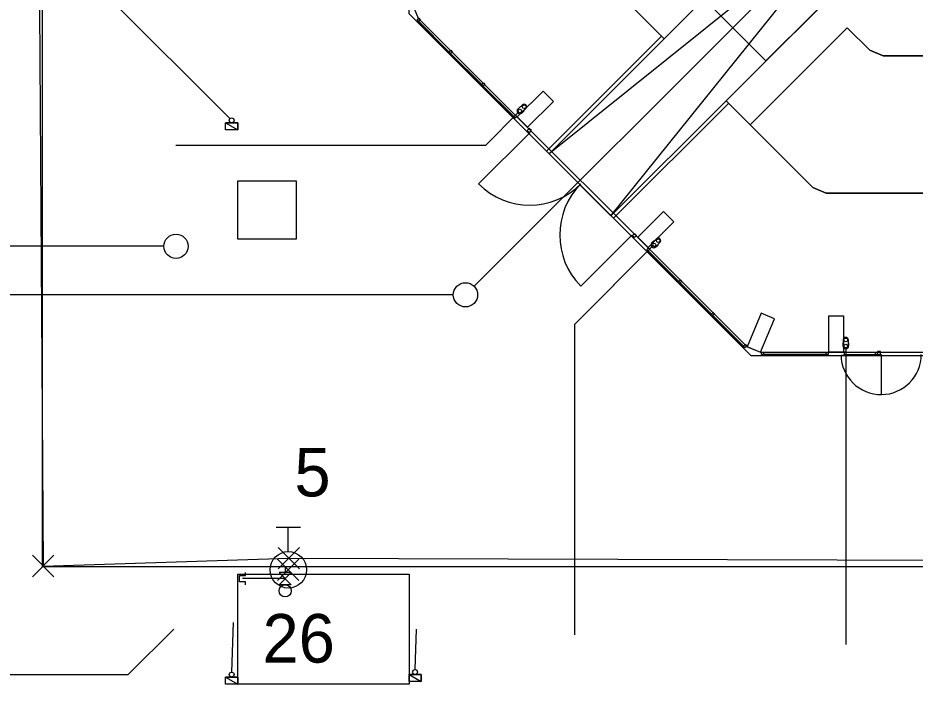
# Model space of a CAD drawing. Extents: x -263964 to -263544, y -1242317 to -1242020.
# Drawn here: x -263925.14 to -263888.22, y -1242254.98 to -1242227.54 of the extents above; entities that cross this region are included whole.
import ezdxf

# ---------------------------------------------------------------- set-up
doc = ezdxf.new("R2010")
doc.units = 0
for name, color, linetype in [('KFA_KOORDINACNA_SITUACIA_DSP_SEDA', 7, 'Continuous'), ('KFA_SO_50-2_POZIARNY_VODOVOD_BODY', 7, 'Continuous'), ('KFA_SO_50-2_POZIARNY_VODOVOD_NADZEMNE_PRVKY', 7, 'Continuous'), ('KFA_SO_50-2_POZIARNY_VODOVOD_TRASA', 7, 'Continuous')]:
    doc.layers.add(name, color=color, linetype=linetype)

msp = doc.modelspace()

# ---------------------------------------------------------------- linework, layer by layer
at = {"layer": 'KFA_KOORDINACNA_SITUACIA_DSP_SEDA'}
for p, q in [((-263924.143, -1242185.14), (-263924.143, -1242250.14)), ((-263889.023, -1242221.253), (-263906.365, -1242238.596)), ((-263916.414, -1242231.691), (-263926.24, -1242221.865)), ((-263908.893, -1242226.995), (-263908.663, -1242227.55)), ((-263908.709, -1242227.631), (-263908.638, -1242227.56)), ((-263908.68, -1242227.659), (-263908.709, -1242227.631)), ((-263908.685, -1242227.654), (-263908.703, -1242227.672)), ((-263907.377, -1242228.963), (-263908.685, -1242227.654)), ((-263908.663, -1242227.55), (-263895.135, -1242241.078)), ((-263908.581, -1242227.617), (-263908.652, -1242227.688)), ((-263908.638, -1242227.56), (-263908.581, -1242227.617)), ((-263908.703, -1242227.672), (-263907.395, -1242228.98)), ((-263908.652, -1242227.688), (-263908.68, -1242227.659)), ((-263895.005, -1242231.945), (-263891.01, -1242227.95)), ((-263891.01, -1242227.95), (-263890.082, -1242228.878)), ((-263907.395, -1242228.98), (-263907.377, -1242228.963)), ((-263907.39, -1242228.95), (-263907.319, -1242228.879)), ((-263907.361, -1242228.978), (-263907.39, -1242228.95)), ((-263907.363, -1242229.012), (-263907.345, -1242228.994)), ((-263906.055, -1242230.32), (-263907.363, -1242229.012)), ((-263907.333, -1242229.007), (-263907.361, -1242228.978)), ((-263907.345, -1242228.994), (-263906.037, -1242230.303)), ((-263907.262, -1242228.936), (-263907.333, -1242229.007)), ((-263907.319, -1242228.879), (-263907.262, -1242228.936)), ((-263890.082, -1242228.878), (-263889.528, -1242229.107)), ((-263889.528, -1242229.107), (-263874.98, -1242229.107)), ((-263906.046, -1242230.294), (-263905.975, -1242230.223)), ((-263905.975, -1242230.223), (-263905.918, -1242230.28)), ((-263906.037, -1242230.303), (-263906.055, -1242230.32)), ((-263906.017, -1242230.322), (-263906.046, -1242230.294)), ((-263906.019, -1242230.356), (-263906.001, -1242230.338)), ((-263904.711, -1242231.664), (-263906.019, -1242230.356)), ((-263905.989, -1242230.351), (-263906.017, -1242230.322)), ((-263906.001, -1242230.338), (-263904.693, -1242231.647)), ((-263905.918, -1242230.28), (-263905.989, -1242230.351)), ((-263903.526, -1242230.561), (-263904.586, -1242231.622)), ((-263903.101, -1242230.985), (-263903.526, -1242230.561)), ((-263904.484, -1242231.218), (-263904.563, -1242231.296)), ((-263904.465, -1242231.218), (-263904.484, -1242231.218)), ((-263904.376, -1242231.13), (-263904.465, -1242231.218)), ((-263904.231, -1242231.275), (-263904.319, -1242231.364)), ((-263904.162, -1242232.046), (-263903.101, -1242230.985)), ((-263904.533, -1242231.432), (-263905.894, -1242232.793)), ((-263904.726, -1242231.613), (-263904.656, -1242231.543)), ((-263904.698, -1242231.642), (-263904.726, -1242231.613)), ((-263904.693, -1242231.647), (-263904.711, -1242231.664)), ((-263904.67, -1242231.67), (-263904.698, -1242231.642)), ((-263904.599, -1242231.599), (-263904.67, -1242231.67)), ((-263904.656, -1242231.543), (-263904.599, -1242231.599)), ((-263904.586, -1242231.622), (-263904.162, -1242232.046)), ((-263904.397, -1242231.462), (-263904.319, -1242231.383)), ((-263904.319, -1242231.383), (-263904.397, -1242231.462)), ((-263904.319, -1242231.364), (-263904.319, -1242231.383)), ((-263916.593, -1242231.862), (-263916.093, -1242231.862)), ((-263916.593, -1242232.152), (-263916.593, -1242231.862)), ((-263916.593, -1242231.862), (-263916.093, -1242232.152)), ((-263916.593, -1242231.862), (-263916.093, -1242232.152)), ((-263916.093, -1242231.862), (-263916.593, -1242231.862)), ((-263916.093, -1242231.862), (-263916.093, -1242232.152)), ((-263916.093, -1242232.152), (-263916.093, -1242231.862)), ((-263892.422, -1242234.528), (-263895.005, -1242231.945)), ((-263916.093, -1242232.152), (-263916.593, -1242232.152)), ((-263904.074, -1242232.281), (-263906.177, -1242234.384)), ((-263904.091, -1242232.093), (-263904.176, -1242232.178)), ((-263904.176, -1242232.178), (-263904.091, -1242232.263)), ((-263904.006, -1242232.178), (-263904.091, -1242232.093)), ((-263904.091, -1242232.263), (-263904.006, -1242232.178)), ((-263904.091, -1242232.263), (-263904.074, -1242232.281)), ((-263905.894, -1242232.793), (-263918.643, -1242232.793)), ((-263916.093, -1242234.257), (-263913.693, -1242234.257)), ((-263916.093, -1242236.657), (-263916.093, -1242234.257)), ((-263913.693, -1242234.257), (-263913.693, -1242236.657)), ((-263891.868, -1242234.757), (-263892.422, -1242234.528)), ((-263874.98, -1242234.757), (-263891.868, -1242234.757)), ((-263899.631, -1242236.576), (-263898.571, -1242235.516)), ((-263898.571, -1242235.516), (-263898.147, -1242235.94)), ((-263898.147, -1242235.94), (-263899.207, -1242237.001)), ((-263899.866, -1242236.488), (-263901.97, -1242238.592)), ((-263899.849, -1242236.506), (-263899.764, -1242236.421)), ((-263899.764, -1242236.591), (-263899.849, -1242236.506)), ((-263899.764, -1242236.421), (-263899.679, -1242236.506)), ((-263899.679, -1242236.506), (-263899.764, -1242236.591)), ((-263913.693, -1242236.657), (-263916.093, -1242236.657)), ((-263899.207, -1242237.001), (-263899.631, -1242236.576)), ((-263898.969, -1242236.733), (-263899.047, -1242236.812)), ((-263898.949, -1242236.733), (-263898.969, -1242236.733)), ((-263898.861, -1242236.645), (-263898.949, -1242236.733)), ((-263898.715, -1242236.791), (-263898.804, -1242236.879)), ((-263898.804, -1242236.879), (-263898.804, -1242236.899)), ((-263919.13, -1242236.949), (-263926.43, -1242236.949)), ((-263898.965, -1242236.895), (-263902.238, -1242240.168)), ((-263899.018, -1242236.948), (-263902.238, -1242240.168)), ((-263899.185, -1242237.014), (-263899.255, -1242237.084)), ((-263899.255, -1242237.084), (-263899.227, -1242237.113)), ((-263899.232, -1242237.108), (-263899.25, -1242237.125)), ((-263899.25, -1242237.125), (-263897.942, -1242238.434)), ((-263897.924, -1242238.416), (-263899.232, -1242237.108)), ((-263899.227, -1242237.113), (-263899.199, -1242237.141)), ((-263899.199, -1242237.141), (-263899.128, -1242237.07)), ((-263899.128, -1242237.07), (-263899.185, -1242237.014)), ((-263898.804, -1242236.899), (-263898.882, -1242236.977)), ((-263898.882, -1242236.977), (-263898.804, -1242236.899)), ((-263897.865, -1242238.333), (-263897.936, -1242238.404)), ((-263897.809, -1242238.389), (-263897.865, -1242238.333)), ((-263897.942, -1242238.434), (-263897.924, -1242238.416)), ((-263897.936, -1242238.404), (-263897.908, -1242238.432)), ((-263897.908, -1242238.432), (-263897.88, -1242238.46)), ((-263897.888, -1242238.452), (-263897.906, -1242238.469)), ((-263897.906, -1242238.469), (-263896.598, -1242239.778)), ((-263896.58, -1242239.76), (-263897.888, -1242238.452)), ((-263897.88, -1242238.46), (-263897.809, -1242238.389)), ((-263907.219, -1242238.949), (-263926.43, -1242238.949)), ((-263896.598, -1242239.778), (-263896.58, -1242239.76)), ((-263896.522, -1242239.677), (-263896.592, -1242239.748)), ((-263896.592, -1242239.748), (-263896.564, -1242239.776)), ((-263896.566, -1242239.809), (-263896.548, -1242239.792)), ((-263895.258, -1242241.118), (-263896.566, -1242239.809)), ((-263896.564, -1242239.776), (-263896.536, -1242239.804)), ((-263896.548, -1242239.792), (-263895.24, -1242241.1)), ((-263896.536, -1242239.804), (-263896.465, -1242239.733)), ((-263896.465, -1242239.733), (-263896.522, -1242239.677)), ((-263894.551, -1242239.702), (-263895.125, -1242241.088)), ((-263893.997, -1242239.932), (-263894.551, -1242239.702)), ((-263891.768, -1242241.312), (-263891.768, -1242239.812)), ((-263891.768, -1242239.812), (-263891.168, -1242239.812)), ((-263891.168, -1242239.812), (-263891.168, -1242241.312)), ((-263902.238, -1242240.168), (-263902.238, -1242252.949)), ((-263894.571, -1242241.318), (-263893.997, -1242239.932)), ((-263891.171, -1242240.932), (-263891.185, -1242240.946)), ((-263891.185, -1242240.946), (-263891.185, -1242241.057)), ((-263891.171, -1242240.807), (-263891.171, -1242240.932)), ((-263890.965, -1242240.807), (-263890.965, -1242240.932)), ((-263890.965, -1242240.932), (-263890.951, -1242240.946)), ((-263890.951, -1242241.057), (-263890.951, -1242240.946)), ((-263890.951, -1242240.946), (-263890.951, -1242241.057)), ((-263895.202, -1242240.996), (-263895.273, -1242241.067)), ((-263895.273, -1242241.067), (-263895.245, -1242241.095)), ((-263895.24, -1242241.1), (-263895.258, -1242241.118)), ((-263895.245, -1242241.095), (-263895.216, -1242241.123)), ((-263895.216, -1242241.123), (-263895.146, -1242241.053)), ((-263895.146, -1242241.053), (-263895.202, -1242240.996)), ((-263895.135, -1242241.078), (-263894.581, -1242241.307)), ((-263895.125, -1242241.088), (-263894.571, -1242241.318)), ((-263894.581, -1242241.307), (-263809.355, -1242241.307)), ((-263894.531, -1242241.407), (-263894.531, -1242241.307)), ((-263894.531, -1242241.307), (-263894.451, -1242241.307)), ((-263894.451, -1242241.307), (-263894.451, -1242241.407)), ((-263891.868, -1242241.407), (-263891.868, -1242241.307)), ((-263891.868, -1242241.307), (-263891.788, -1242241.307)), ((-263891.788, -1242241.307), (-263891.788, -1242241.407)), ((-263891.168, -1242241.312), (-263891.768, -1242241.312)), ((-263891.058, -1242241.307), (-263891.138, -1242241.307)), ((-263891.138, -1242241.307), (-263891.138, -1242241.407)), ((-263891.068, -1242241.132), (-263891.068, -1242253.353)), ((-263891.058, -1242241.407), (-263891.058, -1242241.307)), ((-263889.838, -1242241.407), (-263889.838, -1242241.307)), ((-263889.838, -1242241.307), (-263889.758, -1242241.307)), ((-263889.638, -1242241.287), (-263889.758, -1242241.287)), ((-263889.758, -1242241.287), (-263889.758, -1242241.407)), ((-263889.758, -1242241.307), (-263889.758, -1242241.407)), ((-263889.638, -1242241.407), (-263889.638, -1242241.287)), ((-263894.491, -1242241.407), (-263894.531, -1242241.407)), ((-263894.451, -1242241.407), (-263894.491, -1242241.407)), ((-263891.828, -1242241.407), (-263894.478, -1242241.407)), ((-263894.478, -1242241.407), (-263894.478, -1242241.432)), ((-263894.478, -1242241.432), (-263891.828, -1242241.432)), ((-263891.828, -1242241.407), (-263891.868, -1242241.407)), ((-263891.828, -1242241.432), (-263891.828, -1242241.407)), ((-263891.788, -1242241.407), (-263891.828, -1242241.407)), ((-263891.263, -1242241.432), (-263889.613, -1242241.432)), ((-263891.138, -1242241.407), (-263891.098, -1242241.407)), ((-263891.098, -1242241.432), (-263891.098, -1242241.407)), ((-263891.098, -1242241.407), (-263889.798, -1242241.407)), ((-263891.098, -1242241.407), (-263891.058, -1242241.407)), ((-263889.798, -1242241.432), (-263891.098, -1242241.432)), ((-263889.798, -1242241.407), (-263889.838, -1242241.407)), ((-263889.798, -1242241.407), (-263889.798, -1242241.432)), ((-263889.758, -1242241.407), (-263889.798, -1242241.407)), ((-263889.758, -1242241.407), (-263889.638, -1242241.407)), ((-263889.638, -1242241.407), (-263889.613, -1242241.407)), ((-263889.613, -1242241.407), (-263889.613, -1242243.057)), ((-263924.143, -1242250.14), (-263788.143, -1242250.14)), ((-263914.143, -1242250.14), (-263914.143, -1242250.39)), ((-263914.143, -1242250.14), (-263914.143, -1242250.39)), ((-263916.093, -1242254.982), (-263916.093, -1242250.458)), ((-263916.093, -1242250.458), (-263909.043, -1242250.458)), ((-263916.018, -1242250.515), (-263915.768, -1242250.515)), ((-263916.018, -1242250.765), (-263916.018, -1242250.515)), ((-263915.768, -1242250.515), (-263915.768, -1242250.39)), ((-263914.393, -1242250.39), (-263913.893, -1242250.89)), ((-263913.893, -1242250.39), (-263914.393, -1242250.39)), ((-263914.393, -1242250.89), (-263913.893, -1242250.39)), ((-263909.043, -1242250.458), (-263909.043, -1242254.982)), ((-263915.768, -1242250.765), (-263916.018, -1242250.765)), ((-263914.143, -1242250.64), (-263915.893, -1242250.64)), ((-263915.768, -1242250.89), (-263915.768, -1242250.765)), ((-263913.893, -1242250.89), (-263914.393, -1242250.89)), ((-263920.595, -1242254.592), (-263918.723, -1242252.72)), ((-263916.339, -1242254.492), (-263916.265, -1242252.443)), ((-263908.789, -1242254.387), (-263908.729, -1242252.715)), ((-263929.73, -1242254.592), (-263920.595, -1242254.592)), ((-263909.043, -1242254.587), (-263908.543, -1242254.587)), ((-263909.043, -1242254.877), (-263909.043, -1242254.587)), ((-263909.043, -1242254.587), (-263908.543, -1242254.877)), ((-263909.043, -1242254.587), (-263908.543, -1242254.877)), ((-263908.543, -1242254.587), (-263909.043, -1242254.587)), ((-263908.543, -1242254.587), (-263908.543, -1242254.877)), ((-263908.543, -1242254.877), (-263908.543, -1242254.587)), ((-263916.593, -1242254.692), (-263916.093, -1242254.692)), ((-263916.593, -1242254.982), (-263916.593, -1242254.692)), ((-263916.593, -1242254.692), (-263916.093, -1242254.982)), ((-263916.593, -1242254.692), (-263916.093, -1242254.982)), ((-263916.093, -1242254.692), (-263916.593, -1242254.692)), ((-263916.093, -1242254.692), (-263916.093, -1242254.982)), ((-263916.093, -1242254.982), (-263916.093, -1242254.692)), ((-263908.543, -1242254.877), (-263909.043, -1242254.877)), ((-263916.093, -1242254.982), (-263916.593, -1242254.982)), ((-263909.043, -1242254.982), (-263916.093, -1242254.982))]:
    msp.add_line(p, q, dxfattribs=at)
for points in [[(-263794.893, -1242227.382), (-263808.968, -1242241.457), (-263894.968, -1242241.457), (-263909.043, -1242227.382), (-263909.043, -1242196.333), (-263914.143, -1242196.333), (-263914.143, -1242132.433), (-263909.043, -1242132.433), (-263909.043, -1242101.382), (-263894.968, -1242087.307), (-263808.968, -1242087.307), (-263794.893, -1242101.382), (-263794.893, -1242227.382)], [(-263816.02, -1242224.432), (-263887.916, -1242224.432), (-263888.26, -1242224.088), (-263889.254, -1242226.488), (-263890.391, -1242225.351), (-263894.351, -1242229.311), (-263896.896, -1242226.765), (-263892.937, -1242222.806), (-263894.073, -1242221.669), (-263891.673, -1242220.675), (-263892.018, -1242220.33), (-263892.018, -1242181.432), (-263893.618, -1242181.432), (-263893.618, -1242147.332), (-263892.018, -1242147.332), (-263892.018, -1242108.434)], [(-263898.543, -1242228.407), (-263902.112, -1242224.837), (-263902.343, -1242224.282), (-263902.343, -1242203.332), (-263909.043, -1242203.332)], [(-263891.673, -1242220.675), (-263894.073, -1242221.669), (-263892.937, -1242222.806), (-263898.544, -1242228.407)], [(-263895.995, -1242230.956), (-263890.391, -1242225.352), (-263889.254, -1242226.488), (-263888.26, -1242224.088), (-263891.673, -1242220.675)], [(-263903.277, -1242233.148), (-263900.731, -1242235.694), (-263890.333, -1242222.748), (-263903.277, -1242233.148)], [(-263898.65, -1242228.301), (-263903.39, -1242233.035), (-263900.629, -1242235.796), (-263895.875, -1242231.049)], [(-263898.544, -1242228.407), (-263903.281, -1242233.144), (-263900.731, -1242235.694), (-263895.982, -1242230.943)], [(-263807.942, -1242230.956), (-263811.512, -1242234.526), (-263812.068, -1242234.757), (-263891.868, -1242234.757), (-263892.424, -1242234.526), (-263895.994, -1242230.956)]]:
    msp.add_lwpolyline(points, dxfattribs=at)
msp.add_lwpolyline([(-263891.01, -1242227.95), (-263895.005, -1242231.945), (-263892.422, -1242234.528), (-263891.868, -1242234.757), (-263874.98, -1242234.757), (-263874.98, -1242229.107), (-263889.528, -1242229.107), (-263890.082, -1242228.878)], close=True, dxfattribs=at)
for centre, radius in [((-263904.48, -1242231.379), 0.075), ((-263904.303, -1242231.202), 0.075), ((-263916.343, -1242231.762), 0.1), ((-263918.63, -1242236.949), 0.5), ((-263898.965, -1242236.895), 0.075), ((-263898.788, -1242236.718), 0.075), ((-263906.719, -1242238.949), 0.5), ((-263891.068, -1242240.807), 0.075), ((-263891.068, -1242241.057), 0.075), ((-263914.143, -1242251.14), 0.25), ((-263916.343, -1242254.592), 0.1), ((-263908.793, -1242254.487), 0.1)]:
    msp.add_circle(centre, radius, dxfattribs=at)
for centre, radius, start, end in [((-263904.48, -1242231.379), 0.117, 135, 315), ((-263904.303, -1242231.202), 0.103, 315, 135), ((-263904.074, -1242232.281), 2.975, 225.0001, 315.0001), ((-263899.866, -1242236.488), 2.975, 134.9999, 224.9999), ((-263898.965, -1242236.895), 0.117, 135, 315), ((-263898.788, -1242236.718), 0.103, 315, 135), ((-263891.068, -1242240.807), 0.103, 360, 180), ((-263891.068, -1242241.057), 0.117, 180, 360), ((-263889.613, -1242241.407), 1.65, 180.8682, 0)]:
    msp.add_arc(centre, radius, start, end, dxfattribs=at)
at = {"layer": 'KFA_SO_50-2_POZIARNY_VODOVOD_BODY'}
for p, q in [((-263914.428, -1242250.24), (-263913.544, -1242249.356)), ((-263913.544, -1242250.24), (-263914.428, -1242249.356)), ((-263924.542, -1242250.563), (-263923.658, -1242249.679)), ((-263923.658, -1242250.563), (-263924.542, -1242249.679)), ((-263913.986, -1242249.798), (-263913.986, -1242249.798)), ((-263924.1, -1242250.121), (-263924.1, -1242250.121)), ((-263914.455, -1242250.719), (-263913.571, -1242249.835)), ((-263913.571, -1242250.719), (-263914.455, -1242249.835)), ((-263914.013, -1242250.277), (-263914.013, -1242250.277))]:
    msp.add_line(p, q, dxfattribs=at)
at = {"layer": 'KFA_SO_50-2_POZIARNY_VODOVOD_NADZEMNE_PRVKY'}
for points in [[(-263913.513, -1242248.527), (-263914.513, -1242248.527)], [(-263914.013, -1242249.527), (-263914.013, -1242248.527)]]:
    msp.add_lwpolyline(points, dxfattribs=at)
msp.add_circle((-263914.013, -1242250.277), 0.75, dxfattribs=at)
at = {"layer": 'KFA_SO_50-2_POZIARNY_VODOVOD_TRASA'}
msp.add_lwpolyline([(-263924.931, -1242185.127), (-263924.146, -1242197.091), (-263924.296, -1242220.899), (-263924.1, -1242250.121), (-263913.986, -1242249.798), (-263886.91, -1242249.876), (-263867.714, -1242249.83), (-263837.257, -1242249.836), (-263828.162, -1242249.901), (-263787.99, -1242250.032), (-263788.202, -1242220.837), (-263788.195, -1242200.509), (-263788.092, -1242179.915), (-263788.062, -1242148.958), (-263787.919, -1242127.952), (-263787.952, -1242110.966), (-263788.129, -1242082.536), (-263828.429, -1242082.723), (-263836.783, -1242082.559), (-263867.306, -1242082.615), (-263886.71, -1242082.472), (-263924.08, -1242082.613), (-263924.644, -1242106.322), (-263924.479, -1242117.427)], close=True, dxfattribs=at)

# ---------------------------------------------------------------- texts
at = {"layer": 'KFA_SO_50-2_POZIARNY_VODOVOD_BODY'}
for s, p in [('5', (-263913.758, -1242247.253)), ('26', (-263915.07, -1242254.097))]:
    msp.add_text(s, height=2, dxfattribs=at).set_placement(p)

doc.saveas('drawing.dxf')
